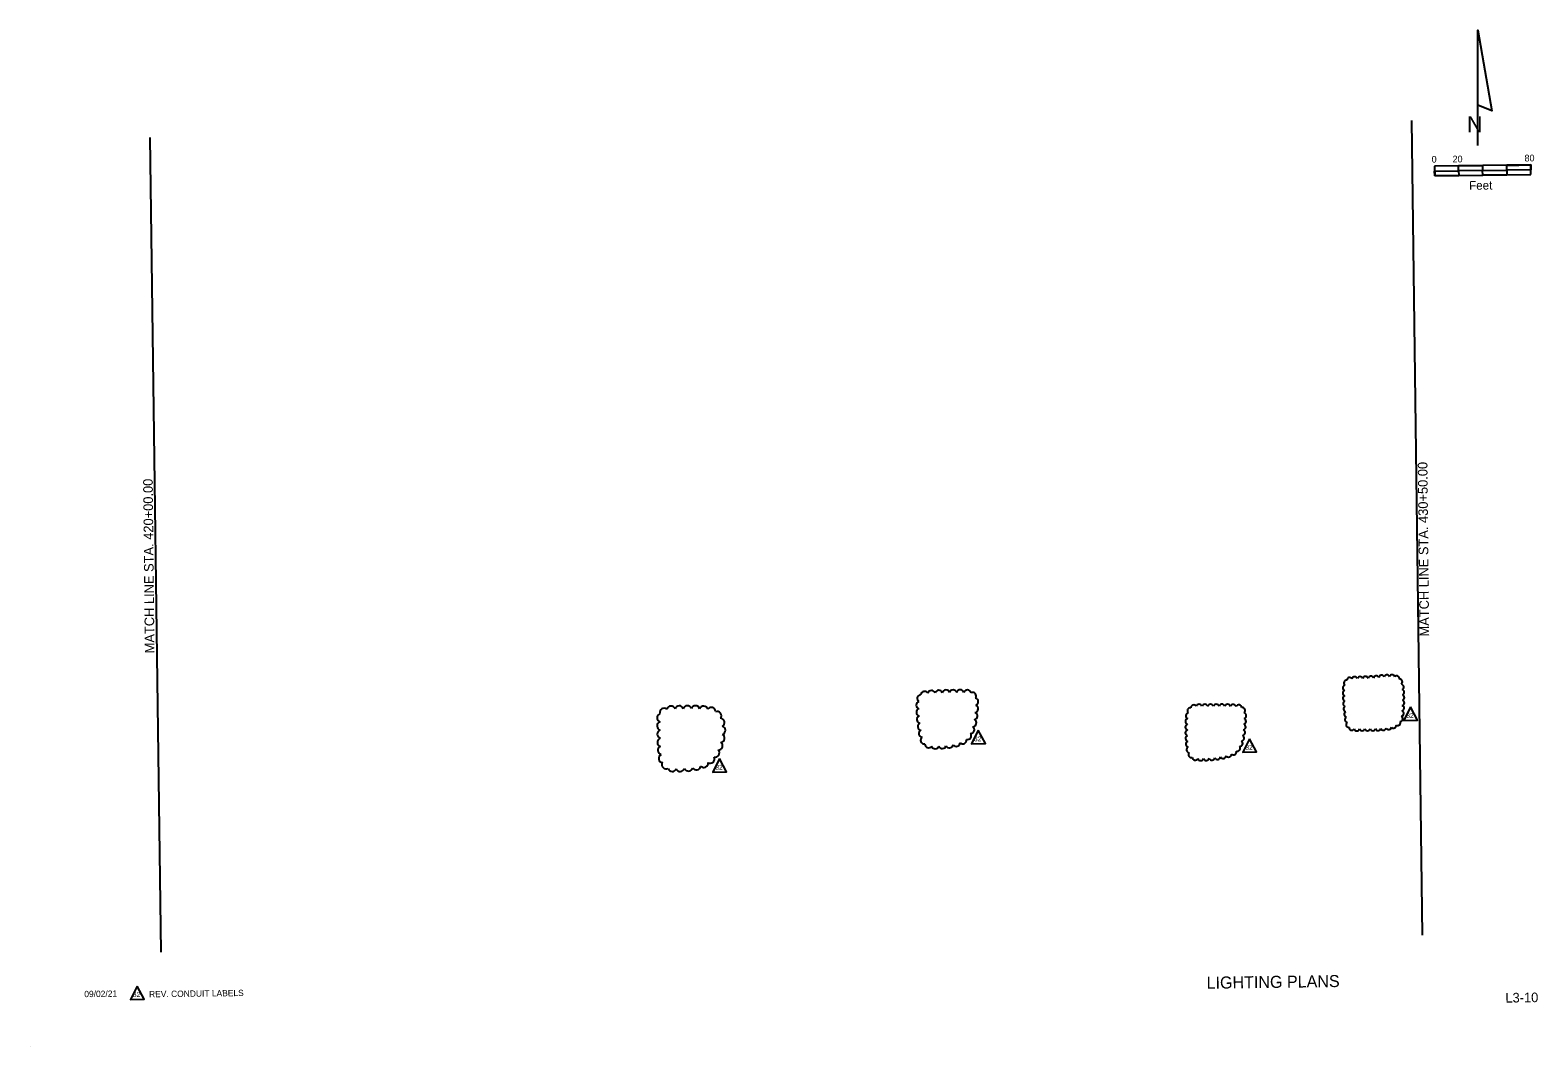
# Model space of a CAD drawing. Extents: x 920305 to 921560, y 636601 to 637448.
import ezdxf

# ---------------------------------------------------------------- set-up
doc = ezdxf.new("R2010")
doc.units = 0
for name, color, linetype in [('AdhocPoint_dp', 7, 'Continuous'), ('Cloud_dp', 7, 'Continuous'), ('MatchLines_dp', 7, 'Continuous'), ('NorthArw_dp', 7, 'Continuous'), ('Scale_dp', 7, 'Continuous'), ('TextLabel', 7, 'Continuous'), ('TextMisc', 7, 'Continuous'), ('TextNotes', 7, 'Continuous'), ('TextShtNo', 7, 'Continuous')]:
    doc.layers.add(name, color=color, linetype=linetype)

msp = doc.modelspace()

# ---------------------------------------------------------------- linework, layer by layer
at = {"layer": 'AdhocPoint_dp'}
msp.add_line((920304.9, 636601.5), (920304.9, 636601.5), dxfattribs=at)
at = {"layer": 'Cloud_dp'}
for points in [[(921453.8, 636884.4), (921448.1, 636873.2), (921459.7, 636873.3)], [(921093.9, 636865), (921088.3, 636853.8), (921099.9, 636854)], [(921319.8, 636858), (921314.2, 636846.8), (921325.7, 636847)], [(920878.7, 636841.4), (920873.1, 636830.2), (920884.6, 636830.3)]]:
    msp.add_lwpolyline(points, close=True, dxfattribs=at)
for centre, radius, start, end in [((921399.7, 636900.4), 2.33, 105.8156, 250.8156), ((921400.6, 636904.4), 2.33, 84.6549, 229.6549), ((921403.1, 636906.6), 2.34, 32.544, 177.544), ((921407.3, 636907.3), 2.33, 20.2913, 165.2913), ((921411.8, 636907.4), 2.33, 18.267, 163.267), ((921416.2, 636907.5), 2.33, 18.267, 163.267), ((921420.7, 636907.7), 2.33, 20.9016, 165.9016), ((921425.2, 636908), 2.33, 23.7104, 168.7104), ((921429.6, 636908.5), 2.33, 23.2799, 168.2799), ((921434, 636908.8), 2.33, 20.3937, 165.3937), ((921438.4, 636908.9), 2.33, 15.207, 160.207), ((921442.3, 636907.9), 2.33, 351.0892, 136.0892), ((921444.7, 636905.2), 2.33, 308.1368, 93.1368), ((921445.8, 636901), 2.33, 295.576, 80.576), ((921045.5, 636885.9), 3.14, 107.303, 252.303), ((921046.3, 636891.5), 3.14, 90.5531, 235.5531), ((921049.4, 636894.3), 3.14, 29.3115, 174.3115), ((921055.1, 636895), 3.14, 19.2726, 164.2726), ((921061.1, 636895.2), 3.14, 19.2726, 164.2726), ((921067.1, 636895.4), 3.14, 19.2593, 164.2593), ((921073.1, 636895.5), 3.14, 18.7735, 163.7735), ((921079, 636895.6), 3.14, 17.6625, 162.6625), ((921085, 636895.5), 3.14, 14.9187, 159.9187), ((921089.2, 636893.4), 3.13, 327.2798, 112.2798), ((921090.9, 636888.7), 3.14, 288.1307, 73.1307), ((921399.7, 636896), 2.33, 108.6941, 253.6941), ((921399.8, 636891.5), 2.33, 110.0647, 255.0647), ((921400, 636887.1), 2.33, 110.9096, 255.9096), ((921446.2, 636896.7), 2.33, 290.2349, 75.2349), ((921446.3, 636892.2), 2.33, 287.7411, 72.7411), ((921446.3, 636887.8), 2.33, 286.2708, 71.2708), ((920830.2, 636875.4), 3.57, 108.267, 253.267), ((920832.5, 636879.8), 3.57, 50.447, 195.447), ((920838.3, 636881.6), 3.57, 19.2967, 164.2967), ((920845.1, 636881.8), 3.57, 19.2212, 164.2212), ((920851.9, 636881.9), 3.57, 18.2469, 163.2469), ((920858.6, 636881.9), 3.57, 16.5376, 161.5376), ((920865.4, 636881.6), 3.57, 13.6254, 158.6254), ((920871.8, 636880.5), 3.57, 0.7813, 145.7813), ((920876.6, 636877.1), 3.57, 324.3016, 109.3016), ((921045.6, 636880), 3.14, 110.7464, 255.7464), ((921046, 636874.1), 3.14, 112.5636, 257.5636), ((921090.2, 636876.9), 3.14, 280.8362, 65.8362), ((921090.8, 636882.8), 3.14, 284.0644, 69.0644), ((921269.3, 636877), 2.49, 101.7615, 246.7615), ((921270.5, 636881.2), 2.49, 80.838, 225.838), ((921273.4, 636883.6), 2.49, 33.2742, 178.2742), ((921277.8, 636884.2), 2.49, 17.5337, 162.5337), ((921282.6, 636884.2), 2.49, 17.398, 162.398), ((921287.3, 636884.2), 2.49, 17.9626, 162.9626), ((921292.1, 636884.2), 2.49, 17.6469, 162.6469), ((921296.8, 636884.3), 2.49, 17.6469, 162.6469), ((921301.5, 636884.2), 2.49, 17.0604, 162.0604), ((921306.2, 636884.1), 2.49, 14.7928, 159.7928), ((921310.9, 636883.6), 2.49, 8.0062, 153.0062), ((921313.6, 636881.5), 2.49, 310.6761, 95.6761), ((921314.5, 636877.2), 2.49, 288.4369, 73.4369), ((921400.3, 636882.7), 2.33, 111.9736, 256.9736), ((921400.8, 636878.3), 2.33, 113.9889, 258.9889), ((921445, 636874.7), 2.33, 274.6433, 59.6433), ((921445.8, 636879), 2.33, 281.1096, 66.1096), ((921446.1, 636883.4), 2.33, 284.2285, 69.2285), ((920830.3, 636868.6), 3.57, 108.267, 253.267), ((920830.4, 636861.8), 3.57, 108.267, 253.267), ((920879.2, 636871.5), 3.57, 300.5617, 85.5617), ((920880, 636865), 3.57, 288.2259, 73.2259), ((921046.7, 636868.2), 3.14, 114.5869, 259.5869), ((921047.6, 636862.3), 3.14, 118.3221, 263.3221), ((921087.7, 636865.5), 3.14, 267.7297, 52.7297), ((921089.3, 636871.1), 3.14, 275.81, 60.81), ((921268.8, 636867.6), 2.49, 107.1219, 252.1219), ((921268.9, 636872.3), 2.49, 105.3861, 250.3861), ((921268.8, 636862.9), 2.49, 108.2497, 253.2497), ((921313.6, 636863.1), 2.49, 280.2189, 65.2189), ((921314.1, 636867.8), 2.49, 283.0328, 68.0328), ((921314.4, 636872.5), 2.49, 284.8945, 69.8945), ((921401.4, 636873.9), 2.33, 117.5453, 262.5453), ((921402.5, 636869.7), 2.34, 126.8306, 271.8306), ((921404.9, 636867.4), 2.33, 180.2538, 325.2538), ((921409, 636866.8), 2.34, 198.267, 343.267), ((921413.5, 636866.9), 2.33, 198.267, 343.267), ((921417.9, 636866.9), 2.33, 198.267, 343.267), ((921422.4, 636867), 2.33, 198.267, 343.267), ((921426.8, 636867.1), 2.33, 198.9867, 343.9867), ((921431.2, 636867.3), 2.33, 202.3865, 347.3865), ((921435.6, 636867.9), 2.33, 207.9511, 352.9511), ((921439.7, 636869.1), 2.33, 218.351, 3.351), ((921443.1, 636871.3), 2.33, 242.6279, 27.6279), ((920830.5, 636855), 3.57, 108.5485, 253.5485), ((920830.8, 636848.3), 3.57, 111.1253, 256.1253), ((920877.7, 636852.1), 3.57, 267.7377, 52.7377), ((920879.4, 636858.4), 3.57, 277.3954, 62.3954), ((921049.2, 636856.8), 3.14, 130.026, 275.026), ((921052.7, 636853.6), 3.13, 179.5976, 324.5976), ((921058.2, 636852.7), 3.14, 196.7779, 341.7779), ((921064.1, 636852.9), 3.14, 201.3678, 346.3678), ((921070, 636853.5), 3.14, 205.2092, 350.2092), ((921075.7, 636854.7), 3.14, 212.9881, 357.9881), ((921081, 636856.8), 3.14, 226.9987, 11.9987), ((921085.1, 636860.5), 3.14, 251.2152, 36.2152), ((921269, 636858.1), 2.49, 109.8085, 254.8085), ((921269.3, 636853.4), 2.49, 112.3884, 257.3884), ((921309.6, 636850.1), 2.49, 252.4881, 37.4881), ((921311.6, 636854.1), 2.49, 268.0935, 53.0935), ((921312.9, 636858.5), 2.49, 275.7133, 60.7133), ((920831.6, 636841.6), 3.57, 117.169, 262.169), ((920870.9, 636841.1), 3.57, 239.5113, 24.5113), ((920875, 636846.1), 3.57, 257.2568, 42.2568), ((921269.9, 636848.8), 2.49, 117.5275, 262.5275), ((921271.4, 636844.7), 2.49, 139.2265, 284.2265), ((921274.5, 636842.6), 2.49, 186.9003, 331.9003), ((921279.1, 636842.2), 2.49, 197.1064, 342.1064), ((921283.8, 636842.3), 2.49, 200.7656, 345.7656), ((921288.5, 636842.6), 2.49, 202.8469, 347.8469), ((921293.2, 636843.2), 2.49, 205.3928, 350.3928), ((921297.8, 636844), 2.49, 209.3575, 354.3575), ((921302.3, 636845.2), 2.49, 215.86, 0.86), ((921306.4, 636847.1), 2.49, 228.6854, 13.6854), ((920834.2, 636836.4), 3.57, 151.7827, 296.7827), ((920839.3, 636834.2), 3.57, 195.7066, 340.7066), ((920846, 636834.2), 3.57, 200.0347, 345.0347), ((920852.8, 636834.6), 3.57, 201.989, 346.989), ((920859.4, 636835.5), 3.57, 209.1512, 354.1512), ((920865.6, 636837.6), 3.57, 222.2484, 7.2484)]:
    msp.add_arc(centre, radius, start, end, dxfattribs=at)
at = {"layer": 'MatchLines_dp'}
for p, q in [((921454.5, 637372.5), (921463.6, 636694.5)), ((920404.6, 637358.5), (920413.7, 636680.4))]:
    msp.add_line(p, q, dxfattribs=at)
at = {"layer": 'NorthArw_dp'}
msp.add_line((921509.9, 637351.8), (921509.9, 637447.8), dxfattribs=at)
msp.add_lwpolyline([(921509.9, 637385.4), (921509.9, 637447.8), (921521.5, 637380.6)], close=True, dxfattribs=at)
at = {"layer": 'Scale_dp'}
for p, q in [((921553.8, 637335.6), (921473.8, 637334.5)), ((921473.8, 637334.5), (921473.9, 637326.5)), ((921553.9, 637327.6), (921553.8, 637335.6)), ((921473.9, 637326.5), (921553.9, 637327.6))]:
    msp.add_line(p, q, dxfattribs=at)
for points in [[(921473.9, 637326.5), (921473.8, 637330.5), (921493.8, 637330.8), (921493.9, 637326.8)], [(921493.8, 637330.8), (921493.8, 637334.8), (921513.8, 637335.1), (921513.8, 637331.1)], [(921513.9, 637327.1), (921513.8, 637331.1), (921533.8, 637331.3), (921533.9, 637327.3)], [(921533.8, 637331.3), (921533.8, 637335.3), (921553.8, 637335.6), (921553.8, 637331.6)]]:
    msp.add_lwpolyline(points, close=True, dxfattribs=at)
at = {"layer": 'TextNotes'}
msp.add_lwpolyline([(920394, 636652.1), (920388.3, 636640.9), (920399.9, 636641.1)], close=True, dxfattribs=at)

# ---------------------------------------------------------------- texts
at = {"layer": 'Cloud_dp'}
for p in [(921450.3, 636875.2), (921090.5, 636855.8), (921316.4, 636848.8), (920875.3, 636832.2)]:
    msp.add_text('32', height=3.94, rotation=0.767, dxfattribs=at).set_placement(p)
at = {"layer": 'MatchLines_dp'}
for s, p in [('MATCH LINE STA. 430+50.00', (921469.3, 636943.1)), ('MATCH LINE STA. 420+00.00', (920408.4, 636929.1))]:
    msp.add_text(s, height=8, rotation=90.583, dxfattribs=at).set_placement(p)
at = {"layer": 'NorthArw_dp'}
msp.add_text('N', height=13.4, dxfattribs=at).set_placement((921500.8, 637362.7))
at = {"layer": 'Scale_dp'}
for s, height, p in [('0', 5.6, (921471.4, 637337.5)), ('20', 5.6, (921488.8, 637337.7)), ('80', 5.6, (921548.7, 637338.5)), ('Feet', 7.2, (921502.6, 637314.9))]:
    msp.add_text(s, height=height, rotation=0.767, dxfattribs=at).set_placement(p)
at = {"layer": 'TextLabel'}
for s, p in [('09/02/21', (920350, 636642.8)), ('REV. CONDUIT LABELS', (920403.9, 636642.7))]:
    msp.add_text(s, height=5.25, rotation=0.767, dxfattribs=at).set_placement(p)
at = {"layer": 'TextMisc'}
msp.add_text('        LIGHTING PLANS         ', height=10, rotation=0.767, dxfattribs=at).set_placement((921254.4, 636649.4))
at = {"layer": 'TextNotes'}
msp.add_text('32', height=3.94, rotation=0.767, dxfattribs=at).set_placement((920390.5, 636642.9))
at = {"layer": 'TextShtNo'}
msp.add_text('L3-10 ', height=8, rotation=0.767, dxfattribs=at).set_placement((921532.8, 636638.3))

doc.saveas('drawing.dxf')
